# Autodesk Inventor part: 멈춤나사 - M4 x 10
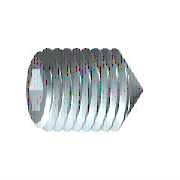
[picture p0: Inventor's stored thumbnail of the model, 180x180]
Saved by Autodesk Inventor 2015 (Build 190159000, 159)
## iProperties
Created: 2012-02
Part Number: 멈춤나사 - M4 x 10
Material: 강철, 연강
Description: 6각 소켓 머리 없는 멈춤 나사
Document SubType Name: Modeling
Standard: KS B 1028
Designer: mduedu
Standards Organization: KS
Language: ko-KR
Size Designation: 원추점 M4x10
Categories: <MemberInstance><Categories><Category DisplayName="조임쇠" InternalName="e4da775c-781d-43d5-af7c-5136215cf5a6" Mnemonic="FSTN"><Category DisplayName="볼트" InternalN
Density: 7.86 g/cm^3
Mass: 0.792069 g
Surface Area: 1.48192 cm^2
Volume: 0.100772 cm^3
Appearance: 강철
Author: mduedu
IsCustomPart: 1
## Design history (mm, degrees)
sketch "스케치1"
  geometry: L1 (0, 0)-(6.833, 0); L2 (10, 1.155)-(10, 2); L3 (10, 2)-(0, 2); L4 (10, 1.155)-(7.5, 1.155); L5 (7.5, 1.155)-(6.833, 0); L6 (0, -0.4)-(0, 2.4) reference; L7 (0, 2)-(0, 0)
  constraints: 13 end point, 3 parallel, 1 collinear, 1 perpendicular, 1 point on line
  dimensions: "d0" = 2.5 distance of L2.start L4.end (= INTI); "d1" = 60 deg angle of L5 L1; "d2" = 4 diameter of L3 L1 (= NND); "d3" = 2.3094 diameter of L4 L1 (= 1.1547 x SW); "d5" = 10 distance from line of L2 L3.end (= NLG)
revolve "본체" sketch "스케치1" stored, may be unused: angle "d6" = 90 deg
sketch "스케치2"
  geometry: L1 (-0.577, 1)-(0.577, 1); L2 (0.577, 1)-(1.155, 0); L3 (1.155, 0)-(0.577, -1); L4 (0.577, -1)-(-0.577, -1); L5 (-0.577, -1)-(-1.155, 0); L6 (-1.155, 0)-(-0.577, 1); 3 further points
  constraints: 12 end point, 1 coincident, 1 horizontal, 13 other
extrude "슬롯" join sketch "스케치2" taper "d7" = 0 deg; stored distance "d21" = 10
workaxis "Work Axis1"
workplane "Work Plane1"
sketch "스케치4"
  geometry: L1 (-5, 0.2)-(-3.2, 2) reference; L2 (-5, -0.2)-(-3.2, -2) reference; L3 (-3.2, 2)-(-5.2, 0); L4 (-3.2, -2)-(-5.2, 0); 2 further points
  constraints: 4 end point, 2 collinear, 1 coincident
body "Solid1"
feature "스레드" dims "d12" = 10 (= NLG), "d13" = 0
chamfer "모따기1" distance "d8" = 1.8 (computed from NND, SPD, FAWI); stored, may be unused: angle "d9" = 45 deg (= FAWI), second distance "d34" = 1.8 (computed from NND, SPD, FAWI)
chamfer "모따기2" distance "d10" = 0.42941 (= -0.5 x GD1 + 0.5 x NND); stored, may be unused: angle "d11" = 45 deg (= FAWI), second distance "d35" = 0.42941 (= -0.5 x GD1 + 0.5 x NND)
other parameters: "NND" = 4 [user parameter; used in 5 equation terms], "NLG" = 10 [user parameter; used in 2 equation terms], "INTI" = 2.5 [user parameter; used in 1 equation term], "FAWI" = 45 deg [user parameter; used in 4 equation terms], "SW" = 2 [user parameter; used in 2 equation terms], "GD1" = 3.14117 (= THREADDIA - 1.2269 x PTC) [user parameter; used in 2 equation terms], "d4" = 0, "FAWI1" = 45 deg [user parameter], "SPD" = 0.4 [user parameter; used in 2 equation terms], "d36" = 0, "d37" = 0, "GUL" = 0.42941 (= 0.61345 x PTC) [user parameter], "TPU" = 14.28571 (computed from PTC) [user parameter], "TOA" = 30 deg [user parameter], "THREADDIA" = 4 [user parameter; used in 1 equation term], "PTC" = 0.7 [user parameter; used in 4 equation terms], "GAL" = 0.42941 (= 0.61345 x PTC) [user parameter], "E0" = 2.31 (= 1.155 x SW) [user parameter]
